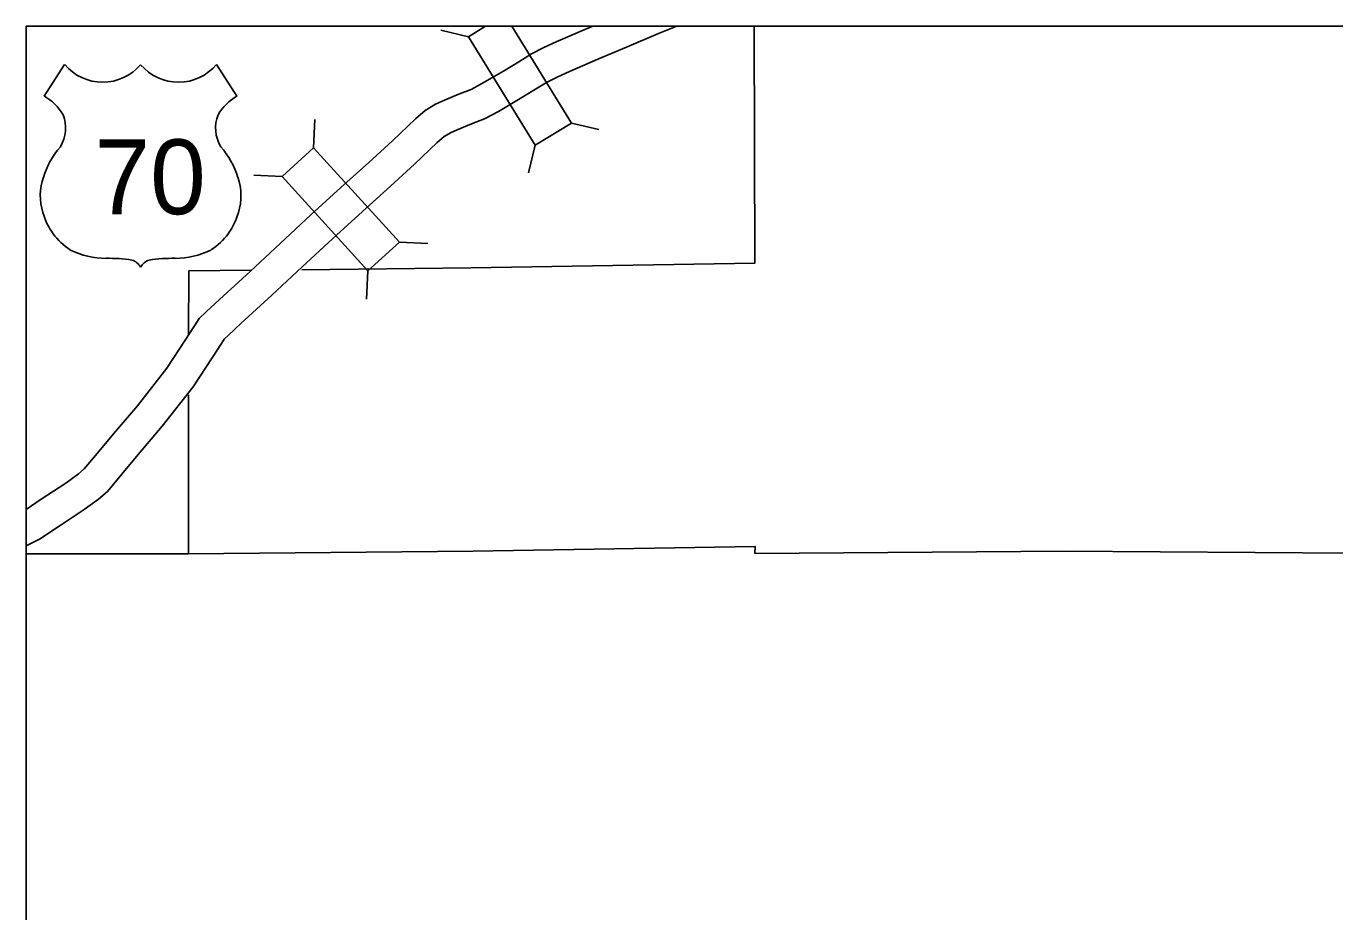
# Model space of a CAD drawing. Extents: x 1373862 to 1377080, y 1164775 to 1170415.
# Drawn here: x 1373884.5 to 1374006.5, y 1170306.2 to 1170388.8 of the extents above; entities that cross this region are included whole.
import ezdxf

# ---------------------------------------------------------------- set-up
doc = ezdxf.new("R2010")
doc.units = 0
doc.layers.add('1', color=7, linetype='Continuous')
doc.layers.add('Default', color=7, linetype='Continuous')

msp = doc.modelspace()

# ---------------------------------------------------------------- linework, layer by layer
at = {"layer": '1'}
msp.add_lwpolyline([(1373884.49, 1170388.77), (1374613.88, 1170388.77), (1374613.88, 1169861.94), (1373884.49, 1169861.94)], close=True, dxfattribs=at)
at = {"layer": 'Default'}
for p, q in [((1373925.71, 1170387.79), (1373923.15, 1170388.41)), ((1373888.07, 1170385.2), (1373886.17, 1170382.25)), ((1373902.23, 1170385.2), (1373904.13, 1170382.25)), ((1373911.27, 1170377.42), (1373911.39, 1170380.06)), ((1373935.31, 1170379.74), (1373937.87, 1170379.13)), ((1373931.93, 1170377.67), (1373931.32, 1170375.1)), ((1373908.34, 1170374.75), (1373905.7, 1170374.88)), ((1373919.27, 1170368.64), (1373921.91, 1170368.52)), ((1373916.34, 1170365.97), (1373916.22, 1170363.34))]:
    msp.add_line(p, q, dxfattribs=at)
for points in [[(1373945.12, 1170388.77), (1373943.42, 1170388.08), (1373940.43, 1170386.83), (1373937.76, 1170385.71), (1373935.12, 1170384.55), (1373934.03, 1170384.06), (1373933.04, 1170383.56), (1373931.97, 1170382.9), (1373930.53, 1170382.02), (1373928.5, 1170380.83), (1373927.21, 1170380.14), (1373926, 1170379.68), (1373924.67, 1170379.12), (1373924.05, 1170378.84), (1373923.45, 1170378.48), (1373922.8, 1170377.92), (1373920.68, 1170375.91), (1373918.44, 1170373.85), (1373915.82, 1170371.51), (1373913.06, 1170368.99), (1373910.19, 1170366.31), (1373907.39, 1170363.71), (1373904.52, 1170361.08), (1373903.33, 1170359.99), (1373902.95, 1170359.61), (1373902.68, 1170359.21), (1373901.81, 1170357.88), (1373900.05, 1170355.15), (1373897.17, 1170351.49), (1373894.92, 1170348.85), (1373893.41, 1170347.03), (1373892.06, 1170345.4), (1373891.22, 1170344.68), (1373889.88, 1170343.73), (1373887.55, 1170342.18), (1373885.72, 1170340.96), (1373884.55, 1170340.38), (1373884.49, 1170340.35)], [(1373937.3, 1170388.77), (1373936.57, 1170388.47), (1373933.9, 1170387.3), (1373932.74, 1170386.77), (1373931.58, 1170386.18), (1373930.4, 1170385.46), (1373928.99, 1170384.59), (1373927.03, 1170383.45), (1373925.97, 1170382.88), (1373924.89, 1170382.46), (1373923.47, 1170381.87), (1373922.64, 1170381.49), (1373921.68, 1170380.91), (1373920.79, 1170380.14), (1373918.64, 1170378.1), (1373916.42, 1170376.07), (1373913.81, 1170373.73), (1373911.03, 1170371.2), (1373908.15, 1170368.51), (1373905.35, 1170365.92), (1373902.49, 1170363.29), (1373901.26, 1170362.16), (1373900.62, 1170361.53), (1373900.17, 1170360.86), (1373899.29, 1170359.51), (1373897.61, 1170356.9), (1373894.85, 1170353.39), (1373892.62, 1170350.78), (1373891.11, 1170348.95), (1373889.9, 1170347.51), (1373889.36, 1170347.04), (1373888.18, 1170346.2), (1373885.89, 1170344.68), (1373884.49, 1170343.74)], [(1373952.35, 1170388.77), (1373952.4, 1170366.68), (1373925.94, 1170366.25), (1373910.19, 1170366.07)], [(1373927.3, 1170388.77), (1373925.71, 1170387.79), (1373931.93, 1170377.67), (1373935.31, 1170379.74), (1373929.76, 1170388.77)], [(1373905.46, 1170366.02), (1373899.64, 1170365.96), (1373899.63, 1170360)], [(1373899.62, 1170354.43), (1373899.61, 1170339.6)], [(1374030.27, 1170339.27), (1374007.88, 1170339.67), (1373981.34, 1170339.86), (1373952.41, 1170339.64), (1373952.43, 1170340.29), (1373926.15, 1170339.86), (1373899.6, 1170339.6), (1373884.49, 1170339.59)]]:
    msp.add_lwpolyline(points, dxfattribs=at)
msp.add_lwpolyline([(1373908.34, 1170374.75), (1373916.34, 1170365.97), (1373919.27, 1170368.64), (1373911.27, 1170377.42)], close=True, dxfattribs=at)
for centre, radius, start, end in [((1373891.62, 1170388.18), 4.63, 220.075, 319.6701), ((1373898.68, 1170388.18), 4.63, 220.3299, 319.925), ((1373883.68, 1170377.98), 4.95, 30.7809, 59.9883), ((1373906.62, 1170377.98), 4.95, 120.0117, 149.2191), ((1373884.77, 1170379.29), 3.39, 328.8105, 21.2108), ((1373905.53, 1170379.29), 3.39, 158.7892, 211.1895), ((1373893.64, 1170372.33), 7.91, 138.9565, 162.6913), ((1373896.67, 1170372.33), 7.91, 17.3087, 41.0435), ((1373891.03, 1170372.98), 5.23, 160.9576, 197.3819), ((1373899.28, 1170372.98), 5.23, 342.6181, 19.0424), ((1373891.88, 1170373), 6.05, 195.1074, 237.1312), ((1373898.43, 1170373), 6.05, 302.8688, 344.8926), ((1373891.99, 1170374.9), 7.77, 244.0771, 269.5779), ((1373892.17, 1170352.91), 14.23, 81.1942, 90.9539), ((1373893.95, 1170365.67), 1.36, 28.0342, 72.9864), ((1373896.36, 1170365.67), 1.36, 107.0136, 151.9658), ((1373898.13, 1170352.91), 14.23, 89.0461, 98.8058), ((1373898.31, 1170374.9), 7.77, 270.4221, 295.9229)]:
    msp.add_arc(centre, radius, start, end, dxfattribs=at)

# ---------------------------------------------------------------- texts
msp.add_text('70', height=6.97, dxfattribs=at).set_placement((1373890.86, 1170371.25))

doc.saveas('drawing.dxf')
